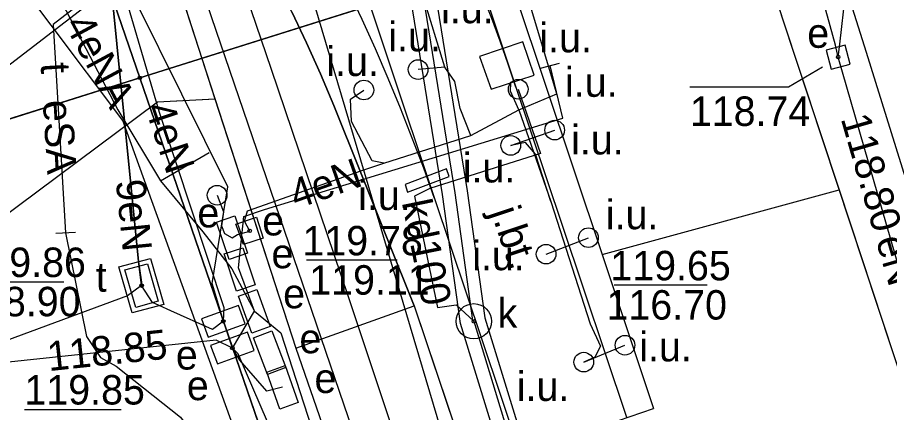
# Model space of a CAD drawing. Extents: x 6432121 to 6432331, y 5662538 to 5662686.
# Drawn here: x 6432243.57 to 6432265.79, y 5662627.61 to 5662637.67 of the extents above; entities that cross this region are included whole.
import ezdxf

# ---------------------------------------------------------------- set-up
doc = ezdxf.new("R2010")
doc.units = 0
for name, color, linetype in [('Warstwa 1', 7, 'Continuous'), ('Warstwa 10', 7, 'Continuous'), ('Warstwa 11', 7, 'Continuous'), ('Warstwa 12', 7, 'Continuous'), ('Warstwa 13', 7, 'Continuous'), ('Warstwa 14', 7, 'Continuous'), ('Warstwa 15', 7, 'Continuous'), ('Warstwa 2', 7, 'Continuous'), ('Warstwa 20', 7, 'Continuous'), ('Warstwa 21', 7, 'Continuous'), ('Warstwa 24', 7, 'Continuous'), ('Warstwa 37', 7, 'Continuous'), ('Warstwa 4', 7, 'Continuous'), ('Warstwa 5', 7, 'Continuous'), ('Warstwa 6', 7, 'Continuous'), ('Warstwa 61', 7, 'Continuous'), ('Warstwa 8', 7, 'Continuous'), ('Warstwa 9', 7, 'Continuous')]:
    doc.layers.add(name, color=color, linetype=linetype)

msp = doc.modelspace()

# ---------------------------------------------------------------- linework, layer by layer
at = {"layer": 'Warstwa 1'}
for p, q in [((6432246.69, 5662636.13), (6432267.75, 5662642.76)), ((6432246.69, 5662636.13), (6432267.75, 5662642.76)), ((6432245.39, 5662639.916), (6432246.69, 5662636.13)), ((6432245.39, 5662639.916), (6432246.69, 5662636.13)), ((6432228.29, 5662630.34), (6432246.69, 5662636.13)), ((6432228.29, 5662630.34), (6432246.69, 5662636.13)), ((6432246.69, 5662636.13), (6432263.163, 5662588.197)), ((6432246.69, 5662636.13), (6432263.163, 5662588.197))]:
    msp.add_line(p, q, dxfattribs=at)
at = {"layer": 'Warstwa 10'}
for points in [[(6432246.23, 5662638.85), (6432244.48, 5662637.49), (6432244.8, 5662632.18)], [(6432244.8, 5662632.18), (6432245.33, 5662629.54), (6432245.69, 5662629.01), (6432246.09, 5662628.79), (6432247.73, 5662627.49), (6432248.93, 5662625.88), (6432257.3, 5662602.44), (6432259.59, 5662595.58)]]:
    msp.add_lwpolyline(points, dxfattribs=at)
at = {"layer": 'Warstwa 11'}
for points in [[(6432249.66, 5662632.58), (6432249.83, 5662632.05), (6432249.33, 5662631.89), (6432249.14, 5662632.4)], [(6432246.16, 5662631.32), (6432246.96, 5662631.53), (6432247.3, 5662630.36), (6432246.5, 5662630.15)]]:
    msp.add_lwpolyline(points, close=True, dxfattribs=at)
msp.add_circle((6432255.2, 5662629.93), 0.45, dxfattribs=at)
at = {"layer": 'Warstwa 12'}
msp.add_line((6432249.05, 5662629.25), (6432249.61, 5662630.185), dxfattribs=at)
for points in [[(6432248.82, 5662629.93), (6432248.54, 5662629.72), (6432247.48, 5662630.2), (6432247.186, 5662630.33), (6432247.012, 5662630.407), (6432246.73, 5662630.84), (6432246.374, 5662630.582), (6432219.55, 5662620.66), (6432213.49, 5662610.33), (6432213.18, 5662609.798), (6432212.84, 5662609.97), (6432201.94, 5662619.39), (6432188.48, 5662659.63), (6432188.372, 5662660.264), (6432188.26, 5662660.96), (6432187.54, 5662663.58), (6432189.456, 5662664.144), (6432190.073, 5662664.038), (6432190.591, 5662664.478), (6432199.77, 5662667.18), (6432202.78, 5662668.86), (6432236.07, 5662677.73), (6432238.751, 5662681.053)], [(6432260.149, 5662593.584), (6432259.505, 5662597.442), (6432258.113, 5662602.229), (6432246.261, 5662635.045), (6432242.6, 5662639.91), (6432237.105, 5662644.467), (6432235.235, 5662651.91), (6432228.3, 5662671.335), (6432227.148, 5662676.149), (6432227.614, 5662677.443), (6432228.191, 5662677.996), (6432231.551, 5662678.816), (6432233.235, 5662681.053)], [(6432251.161, 5662678.636), (6432251.195, 5662678.505), (6432250.722, 5662667.538), (6432250.449, 5662664.161), (6432250.95, 5662660.785), (6432251.946, 5662652.429), (6432252.859, 5662647.409), (6432253.435, 5662643.141), (6432255.033, 5662633.254), (6432255.483, 5662630.016), (6432258.492, 5662620.223), (6432259.57, 5662616.642), (6432259.85, 5662615.749), (6432260.538, 5662613.47), (6432262.28, 5662607.688), (6432262.524, 5662606.965), (6432264.736, 5662599.765)], [(6432264.124, 5662599.577), (6432261.914, 5662606.769), (6432261.67, 5662607.494), (6432259.926, 5662613.286), (6432259.238, 5662615.561), (6432258.958, 5662616.454), (6432257.88, 5662620.037), (6432254.857, 5662629.878), (6432254.401, 5662633.158), (6432252.801, 5662643.047), (6432252.227, 5662647.309), (6432251.312, 5662652.333), (6432250.316, 5662660.701), (6432249.805, 5662664.139), (6432250.084, 5662667.578), (6432250.551, 5662678.439), (6432250.541, 5662678.478)], [(6432258.356, 5662662.998), (6432258.39, 5662658.398), (6432260.508, 5662651.738), (6432262.768, 5662644.481), (6432265.197, 5662636.781), (6432267.384, 5662629.75), (6432269.748, 5662622.257), (6432272.462, 5662613.493), (6432273.441, 5662610.386), (6432276.081, 5662601.737), (6432278.642, 5662593.628), (6432281.263, 5662585.188), (6432283.543, 5662577.76), (6432283.852, 5662577.022), (6432284.284, 5662575.255)], [(6432244.451, 5662661.055), (6432244.51, 5662660.562), (6432244.747, 5662659.597), (6432247.148, 5662651.498), (6432250.159, 5662641.297), (6432254.564, 5662626.481), (6432257.548, 5662616.394), (6432260.807, 5662605.248), (6432262.453, 5662599.664), (6432266.272, 5662586.802), (6432268.265, 5662580.011), (6432268.423, 5662579.446)], [(6432243.958, 5662654.289), (6432246.621, 5662646.365), (6432250.032, 5662636.381), (6432251.998, 5662630.56), (6432253.864, 5662624.956), (6432256.122, 5662618.174), (6432258.071, 5662612.417), (6432261.076, 5662603.597), (6432261.907, 5662601.278), (6432263.382, 5662596.576), (6432264.52, 5662593.503), (6432265.328, 5662591.162), (6432268.156, 5662582.752), (6432268.733, 5662580.715)], [(6432243.16, 5662653.357), (6432252.465, 5662626.114), (6432254.893, 5662619.007), (6432257.883, 5662610.233), (6432261.03, 5662600.869), (6432263.754, 5662592.896), (6432267.107, 5662583.22), (6432267.857, 5662579.356), (6432269.061, 5662572.854)], [(6432246.73, 5662630.84), (6432246.66, 5662631.45), (6432245.74, 5662640.67), (6432245.267, 5662641.347), (6432244.6, 5662641.33), (6432196.62, 5662630.41), (6432162.36, 5662620.4), (6432161.76, 5662619.96), (6432161.08, 5662620.39), (6432144.64, 5662638.75), (6432139.05, 5662643.99), (6432134.66, 5662649.12), (6432133.76, 5662650.98), (6432133.196, 5662651.358)], [(6432264.48, 5662636.66), (6432264.52, 5662636.99), (6432264.81, 5662639.54), (6432266.05, 5662643.74), (6432265.984, 5662647.596), (6432266.37, 5662648.378)], [(6432245.267, 5662641.347), (6432245.74, 5662640.67), (6432246.66, 5662631.45), (6432246.75, 5662630.81)], [(6432248.82, 5662629.93), (6432248.531, 5662630.897), (6432248.931, 5662633.353), (6432245.428, 5662640.425), (6432245.267, 5662641.347)], [(6432248.82, 5662629.93), (6432248.84, 5662630.27), (6432247.19, 5662635.25), (6432246.08, 5662639.03), (6432245.474, 5662640.464), (6432245.267, 5662641.347)], [(6432264.48, 5662636.66), (6432264.41, 5662636.96), (6432263.716, 5662639.493)], [(6432244.181, 5662639.26), (6432244.403, 5662638.629), (6432246.131, 5662635.318), (6432247.214, 5662633.504), (6432248.295, 5662632.211), (6432249.036, 5662631.265), (6432249.61, 5662630.185)], [(6432256.35, 5662635.32), (6432257.31, 5662635.72), (6432256.26, 5662639.24), (6432255.88, 5662639.09)], [(6432246.23, 5662638.85), (6432244.48, 5662637.49), (6432244.8, 5662632.18)], [(6432254.46, 5662636.4), (6432253.91, 5662638.21), (6432254.04, 5662638.51), (6432254.5, 5662638.68)], [(6432268.05, 5662624.31), (6432264.48, 5662636.66)], [(6432249.61, 5662630.185), (6432249.209, 5662631.289), (6432249.339, 5662632.602), (6432249.866, 5662632.778), (6432257.469, 5662635.101), (6432257.144, 5662636.442)], [(6432254.46, 5662636.4), (6432253.78, 5662636.34)], [(6432255.12, 5662634.66), (6432254.85, 5662635.35), (6432254.72, 5662636.04), (6432254.46, 5662636.4)], [(6432256.35, 5662635.32), (6432256.13, 5662635.79), (6432256.141, 5662636.004)], [(6432252.91, 5662633.96), (6432252.61, 5662634.02), (6432252.08, 5662635.02), (6432252.06, 5662635.59), (6432252.4, 5662635.82)], [(6432256.33, 5662635.84), (6432256.9, 5662634.2), (6432254.08, 5662633.31), (6432253.69, 5662633.12), (6432254.27, 5662630.28), (6432254.75, 5662630.35), (6432255.2, 5662629.93)], [(6432255.12, 5662634.66), (6432256.35, 5662635.32)], [(6432256.35, 5662635.32), (6432257.16, 5662632.98)], [(6432252.91, 5662633.96), (6432255.12, 5662634.66)], [(6432257.16, 5662632.98), (6432256.77, 5662634.19), (6432256.52, 5662634.48), (6432256.14, 5662634.41), (6432257.26, 5662634.8)], [(6432247.214, 5662633.504), (6432248.455, 5662634.227)], [(6432249.04, 5662632.06), (6432249.18, 5662632.14), (6432249.49, 5662632.23), (6432249.36, 5662632.48), (6432249.43, 5662632.74), (6432252.35, 5662633.77), (6432252.91, 5662633.96)], [(6432248.66, 5662633.14), (6432248.82, 5662632.72), (6432248.77, 5662632.36), (6432248.85, 5662632.17), (6432249.04, 5662632.06)], [(6432257.16, 5662632.98), (6432258.16, 5662629.87), (6432258.43, 5662629.3), (6432258.28, 5662629.02), (6432258, 5662628.89), (6432259.05, 5662629.32)], [(6432244.8, 5662632.18), (6432245.33, 5662629.54), (6432245.69, 5662629.01), (6432246.09, 5662628.79), (6432247.73, 5662627.49), (6432248.93, 5662625.88), (6432257.3, 5662602.44), (6432259.59, 5662595.58)], [(6432257.04, 5662631.64), (6432258.12, 5662632.06)], [(6432249.61, 5662630.185), (6432250.286, 5662629.633), (6432252.331, 5662623.317), (6432254.562, 5662616.419), (6432255.202, 5662614.617), (6432256.008, 5662612.508), (6432256.249, 5662612.065), (6432256.997, 5662609.824), (6432258.713, 5662604.681), (6432261.287, 5662596.72), (6432264.864, 5662586.606), (6432264.777, 5662586.057)], [(6432249.05, 5662629.25), (6432248.82, 5662629.93)], [(6432249.05, 5662629.25), (6432248.64, 5662629.45), (6432162.596, 5662620.344), (6432161.76, 5662619.96)], [(6432264.921, 5662586.356), (6432264.864, 5662586.606), (6432260.124, 5662594.894), (6432256.835, 5662605.655), (6432256.691, 5662608.587), (6432255.365, 5662611.413), (6432254.697, 5662614.101), (6432250.901, 5662625.148), (6432249.199, 5662629.099), (6432249.05, 5662629.25)], [(6432250.325, 5662628.25), (6432249.93, 5662628.15), (6432249.24, 5662628.94), (6432249.05, 5662629.25)]]:
    msp.add_lwpolyline(points, dxfattribs=at)
msp.add_circle((6432246.69, 5662636.13), 0.045, dxfattribs=at)
at = {"layer": 'Warstwa 14'}
for p, q in [((6432253.243, 5662631.489), (6432250.934, 5662631.489)), ((6432242.307, 5662630.933), (6432244.752, 5662630.933)), ((6432261.147, 5662630.853), (6432258.778, 5662630.853)), ((6432243.756, 5662627.686), (6432246.219, 5662627.686))]:
    msp.add_line(p, q, dxfattribs=at)
msp.add_lwpolyline([(6432260.703, 5662635.903), (6432263.218, 5662635.903), (6432264.08, 5662636.41)], dxfattribs=at)
for centre in [(6432264.48, 5662636.66), (6432264.48, 5662636.66), (6432249.49, 5662632.234), (6432246.736, 5662630.838), (6432248.82, 5662629.93), (6432248.82, 5662629.93), (6432255.2, 5662629.93), (6432249.05, 5662629.25), (6432249.05, 5662629.25), (6432249.05, 5662629.25), (6432249.05, 5662629.25)]:
    msp.add_circle(centre, 0.045, dxfattribs=at)
at = {"layer": 'Warstwa 2'}
msp.add_circle((6432248.66, 5662633.14), 0.25, dxfattribs=at)
at = {"layer": 'Warstwa 20'}
for p, q in [((6432256.902, 5662636.38), (6432257.386, 5662636.504)), ((6432245.05, 5662632.195), (6432244.55, 5662632.165)), ((6432245.05, 5662632.195), (6432244.55, 5662632.165))]:
    msp.add_line(p, q, dxfattribs=at)
at = {"layer": 'Warstwa 21'}
for points in [[(6432248.965, 5662631.506), (6432248.642, 5662632.452), (6432249.115, 5662632.614), (6432249.438, 5662631.668), (6432248.965, 5662631.506)], [(6432249.156, 5662630.697), (6432248.839, 5662631.645), (6432249.314, 5662631.803), (6432249.631, 5662630.855), (6432249.156, 5662630.697)], [(6432249.545, 5662629.63), (6432249.205, 5662630.57), (6432249.675, 5662630.74), (6432250.015, 5662629.8), (6432249.545, 5662629.63)], [(6432249.943, 5662628.574), (6432249.59, 5662629.51), (6432250.057, 5662629.686), (6432250.41, 5662628.75), (6432249.943, 5662628.574)], [(6432250.255, 5662627.695), (6432249.923, 5662628.638), (6432250.395, 5662628.805), (6432250.727, 5662627.862), (6432250.255, 5662627.695)]]:
    msp.add_lwpolyline(points, dxfattribs=at)
at = {"layer": 'Warstwa 24'}
for points in [[(6432255.64, 5662635.84), (6432256.74, 5662636.2), (6432256.45, 5662637.05), (6432255.34, 5662636.67)], [(6432253.51, 5662633.22), (6432254.57, 5662633.62), (6432254.5, 5662633.81), (6432253.45, 5662633.41)]]:
    msp.add_lwpolyline(points, close=True, dxfattribs=at)
for centre in [(6432253.78, 5662636.34), (6432252.4, 5662635.82), (6432256.33, 5662635.84), (6432257.26, 5662634.8), (6432256.14, 5662634.41), (6432258.12, 5662632.06), (6432257.04, 5662631.64), (6432259.05, 5662629.32), (6432258, 5662628.89)]:
    msp.add_circle(centre, 0.25, dxfattribs=at)
at = {"layer": 'Warstwa 37'}
for points in [[(6432249.116, 5662650.415), (6432249.248, 5662649.722), (6432249.38, 5662649.03), (6432250.17, 5662645.84), (6432251.85, 5662640.08), (6432254.2, 5662633.06), (6432255.4, 5662629.47), (6432256.37, 5662626.58)], [(6432252.027, 5662650.548), (6432252.197, 5662649.798), (6432252.37, 5662649.049), (6432252.548, 5662648.301), (6432252.73, 5662647.555), (6432252.916, 5662646.809), (6432253.106, 5662646.064), (6432253.3, 5662645.32), (6432253.426, 5662644.858), (6432253.554, 5662644.396), (6432253.685, 5662643.935), (6432253.817, 5662643.474), (6432253.952, 5662643.014), (6432254.088, 5662642.555), (6432254.227, 5662642.096), (6432254.367, 5662641.638), (6432254.51, 5662641.18), (6432256.27, 5662635.89), (6432257.45, 5662632.38), (6432259.09, 5662627.49)], [(6432256.27, 5662635.89), (6432256.075, 5662636.478), (6432255.87, 5662637.062), (6432255.655, 5662637.642), (6432255.43, 5662638.219), (6432255.196, 5662638.792), (6432254.951, 5662639.36), (6432254.697, 5662639.925), (6432254.433, 5662640.485), (6432254.16, 5662641.04), (6432252.94, 5662643.46), (6432251.27, 5662646.32), (6432249.14, 5662649.35), (6432248.723, 5662649.876)], [(6432254.2, 5662633.06), (6432253.923, 5662633.831), (6432253.633, 5662634.598), (6432253.332, 5662635.359), (6432253.018, 5662636.116), (6432252.692, 5662636.868), (6432252.354, 5662637.614), (6432252.005, 5662638.355)]]:
    msp.add_lwpolyline(points, dxfattribs=at)
at = {"layer": 'Warstwa 4'}
for points in [[(6432264.174, 5662636.837), (6432264.303, 5662636.354), (6432264.786, 5662636.483), (6432264.657, 5662636.966)], [(6432249.66, 5662632.58), (6432249.83, 5662632.05), (6432249.33, 5662631.89), (6432249.14, 5662632.4)], [(6432246.31, 5662631.24), (6432246.89, 5662631.39), (6432247.16, 5662630.44), (6432246.59, 5662630.28)], [(6432249.204, 5662630.336), (6432248.265, 5662629.994), (6432248.436, 5662629.524), (6432249.375, 5662629.866)], [(6432249.434, 5662629.656), (6432248.495, 5662629.314), (6432248.666, 5662628.844), (6432249.605, 5662629.186)]]:
    msp.add_lwpolyline(points, close=True, dxfattribs=at)
msp.add_circle((6432255.2, 5662629.93), 0.45, dxfattribs=at)
at = {"layer": 'Warstwa 5'}
for p, q in [((6432241.65, 5662635.152), (6432245.914, 5662638.423)), ((6432241.879, 5662631.601), (6432247.144, 5662635.519)), ((6432247.144, 5662635.519), (6432248.453, 5662635.588)), ((6432248.453, 5662635.588), (6432248.604, 5662635.596)), ((6432248.604, 5662635.596), (6432250.664, 5662629.247)), ((6432250.664, 5662629.247), (6432251.67, 5662626.36))]:
    msp.add_line(p, q, dxfattribs=at)
at = {"layer": 'Warstwa 6'}
for points in [[(6432253.68, 5662630.32), (6432251.63, 5662635.43), (6432251.29, 5662636.231), (6432250.934, 5662637.026), (6432250.563, 5662637.813), (6432250.177, 5662638.593), (6432249.775, 5662639.365), (6432249.359, 5662640.129), (6432248.927, 5662640.885), (6432248.481, 5662641.632), (6432248.02, 5662642.37), (6432247.671, 5662642.917), (6432247.312, 5662643.457), (6432246.944, 5662643.991), (6432246.566, 5662644.519), (6432246.179, 5662645.039), (6432245.783, 5662645.553), (6432245.377, 5662646.059), (6432244.963, 5662646.558), (6432244.54, 5662647.05), (6432244.291, 5662647.324), (6432244.038, 5662647.593), (6432243.779, 5662647.857), (6432243.516, 5662648.117)], [(6432295.199, 5662556.053), (6432289.811, 5662577.223), (6432287.64, 5662583.69), (6432267.75, 5662642.76), (6432246.69, 5662636.13), (6432263.163, 5662588.197), (6432269.007, 5662560.534), (6432269.756, 5662556.053)], [(6432261.53, 5662642.45), (6432261.725, 5662641.888), (6432263.054, 5662637.661), (6432266.526, 5662627.159), (6432271.921, 5662611.052), (6432274.366, 5662604.334), (6432277.03, 5662595.697), (6432280.318, 5662586.138), (6432281.64, 5662582.902)], [(6432253.68, 5662630.32), (6432261.638, 5662606.697), (6432266.51, 5662591.804), (6432267.797, 5662587.848)]]:
    msp.add_lwpolyline(points, dxfattribs=at)
for points in [[(6432245.39, 5662639.916), (6432246.69, 5662636.13), (6432267.75, 5662642.76), (6432266.742, 5662645.747)], [(6432166.394, 5662623.975), (6432164.332, 5662622.19), (6432180.9, 5662615.82), (6432193.86, 5662619.79), (6432228.29, 5662630.34), (6432246.69, 5662636.13), (6432245.39, 5662639.916), (6432234.842, 5662644.244)], [(6432259.074, 5662585.787), (6432263.163, 5662588.197), (6432246.69, 5662636.13), (6432228.29, 5662630.34), (6432193.86, 5662619.79), (6432180.9, 5662615.82)]]:
    msp.add_lwpolyline(points, close=True, dxfattribs=at)
at = {"layer": 'Warstwa 61'}
msp.add_lwpolyline([(6432250.819, 5662681.053), (6432250.821, 5662679.711), (6432250.716, 5662679.086), (6432250.873, 5662678.472), (6432250.403, 5662667.558), (6432250.127, 5662664.15), (6432250.633, 5662660.743), (6432251.629, 5662652.381), (6432252.543, 5662647.359), (6432253.118, 5662643.094), (6432254.717, 5662633.206), (6432255.17, 5662629.947), (6432255.2, 5662629.93), (6432258.186, 5662620.13), (6432259.264, 5662616.548), (6432259.544, 5662615.655), (6432260.232, 5662613.378), (6432261.975, 5662607.591), (6432262.219, 5662606.867), (6432264.43, 5662599.671)], dxfattribs=at)
at = {"layer": 'Warstwa 8'}
for p, q in [((6432261.725, 5662641.888), (6432263.054, 5662637.661)), ((6432255.26, 5662641.23), (6432258.47, 5662631.63)), ((6432255.26, 5662641.23), (6432258.47, 5662631.63)), ((6432250.563, 5662637.813), (6432250.934, 5662637.026)), ((6432263.054, 5662637.661), (6432264.503, 5662633.279)), ((6432250.934, 5662637.026), (6432251.29, 5662636.231)), ((6432251.29, 5662636.231), (6432251.63, 5662635.43)), ((6432251.63, 5662635.43), (6432253.68, 5662630.32)), ((6432258.47, 5662631.63), (6432264.503, 5662633.279)), ((6432258.47, 5662631.63), (6432264.503, 5662633.279)), ((6432264.503, 5662633.279), (6432266.179, 5662628.209)), ((6432258.47, 5662631.63), (6432259.78, 5662627.71)), ((6432258.47, 5662631.63), (6432259.78, 5662627.71)), ((6432253.68, 5662630.32), (6432255.099, 5662626.107)), ((6432257.996, 5662627.099), (6432259.78, 5662627.71)), ((6432257.996, 5662627.099), (6432259.78, 5662627.71))]:
    msp.add_line(p, q, dxfattribs=at)
at = {"layer": 'Warstwa 9'}
for p, q in [((6432261.725, 5662641.888), (6432263.054, 5662637.661)), ((6432247.51, 5662638.97), (6432250.664, 5662629.247)), ((6432247.51, 5662638.97), (6432248.604, 5662635.596)), ((6432241.65, 5662635.152), (6432245.914, 5662638.423)), ((6432250.563, 5662637.813), (6432250.934, 5662637.026)), ((6432263.054, 5662637.661), (6432264.503, 5662633.279)), ((6432250.934, 5662637.026), (6432251.29, 5662636.231)), ((6432251.29, 5662636.231), (6432251.63, 5662635.43)), ((6432241.879, 5662631.601), (6432247.144, 5662635.519)), ((6432247.144, 5662635.519), (6432248.604, 5662635.596)), ((6432251.63, 5662635.43), (6432253.68, 5662630.32)), ((6432264.503, 5662633.279), (6432266.179, 5662628.209)), ((6432250.664, 5662629.247), (6432253.68, 5662630.32)), ((6432250.664, 5662629.247), (6432253.68, 5662630.32)), ((6432253.68, 5662630.32), (6432261.638, 5662606.697)), ((6432250.664, 5662629.247), (6432251.67, 5662626.36))]:
    msp.add_line(p, q, dxfattribs=at)

# ---------------------------------------------------------------- texts
at = {"layer": 'Warstwa 11'}
msp.add_text('eSA', height=0.75, rotation=273.4498, dxfattribs=at).set_placement((6432244.221, 5662635.548))
at = {"layer": 'Warstwa 13'}
for s, rotation, p in [('4eNA', 298.2646, (6432244.759, 5662637.495)), ('t', 273.4498, (6432244.164, 5662636.499)), ('4eN', 288.3296, (6432246.814, 5662635.375)), ('4eN', 19.429, (6432250.674, 5662632.781)), ('9eN', 275.6958, (6432246.078, 5662633.509)), ('kd100', 281.54, (6432253.361, 5662632.96)), ('eN', 286.1237, (6432265.435, 5662632.006))]:
    msp.add_text(s, height=0.75, rotation=rotation, dxfattribs=at).set_placement(p)
at = {"layer": 'Warstwa 14'}
for s, p in [('118.74', (6432260.703, 5662634.906)), ('119.11', (6432251.007, 5662630.609)), ('118.90', (6432242.114, 5662630.058)), ('116.70', (6432258.58, 5662629.974))]:
    msp.add_text(s, height=0.75, dxfattribs=at).set_placement(p)
for s, rotation, p in [('118.80', 286.1237, (6432264.542, 5662635.096)), ('118.85', 6.039, (6432244.372, 5662628.66))]:
    msp.add_text(s, height=0.75, rotation=rotation, dxfattribs=at).set_placement(p)
at = {"layer": 'Warstwa 15'}
for s, p in [('119.78', (6432250.834, 5662631.609)), ('119.86', (6432242.25, 5662631.058)), ('119.65', (6432258.678, 5662630.974)), ('119.85', (6432243.752, 5662627.811))]:
    msp.add_text(s, height=0.75, dxfattribs=at).set_placement(p)
at = {"layer": 'Warstwa 21'}
for p in [(6432248.158, 5662632.322), (6432250.045, 5662631.281), (6432250.342, 5662630.261), (6432250.757, 5662629.116), (6432251.14, 5662628.104)]:
    msp.add_text('e', height=0.75, dxfattribs=at).set_placement(p)
at = {"layer": 'Warstwa 24'}
for p in [(6432254.366, 5662637.522), (6432253.022, 5662636.807), (6432256.87, 5662636.781), (6432251.443, 5662636.178), (6432257.523, 5662635.648), (6432257.679, 5662634.18), (6432254.918, 5662633.467), (6432252.254, 5662632.763), (6432258.563, 5662632.276), (6432255.159, 5662631.232), (6432259.414, 5662628.909), (6432256.294, 5662627.902)]:
    msp.add_text('i.u.', height=0.75, dxfattribs=at).set_placement(p)
at = {"layer": 'Warstwa 5'}
for s, p in [('e', (6432263.694, 5662636.895)), ('e', (6432249.811, 5662632.117)), ('t', (6432245.569, 5662630.684)), ('k', (6432255.808, 5662629.764)), ('e', (6432247.609, 5662628.701)), ('e', (6432247.889, 5662627.922))]:
    msp.add_text(s, height=0.75, dxfattribs=at).set_placement(p)
at = {"layer": 'Warstwa 8'}
msp.add_text('j.bt.', height=0.75, rotation=288.4842, dxfattribs=at).set_placement((6432255.629, 5662632.717))

doc.saveas('drawing.dxf')
